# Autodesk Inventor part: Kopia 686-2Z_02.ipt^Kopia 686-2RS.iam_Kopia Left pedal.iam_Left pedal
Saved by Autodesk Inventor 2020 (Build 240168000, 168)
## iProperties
Created: 2017-10
Part Number: Kopia 686-2Z_02.ipt^Kopia 686-2RS.iam_Kopia Left pedal.iam_Left pedal
Material: Ogólny
Document SubType Name: Modeling
Designer: Tomasz
Density: 1 g/cm^3
Appearance: Domyślna
Sending System: SolidWorks 2017
Last Author: Tomasz
Last Saved: 2017-10-01
Author: Tomasz
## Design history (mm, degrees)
